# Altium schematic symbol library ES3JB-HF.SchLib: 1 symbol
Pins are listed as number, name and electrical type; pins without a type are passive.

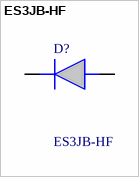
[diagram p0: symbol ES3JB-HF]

## ES3JB-HF
designator D?
Rectifiers RECTIFIER SUPER FAST RECOVERY 600V 3A SMB; Manufacturer_Name: Comchip Technology; Geometry.Height: 2.44mm
footprint DIOM5235X244N
pins: 1 K, 2 A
